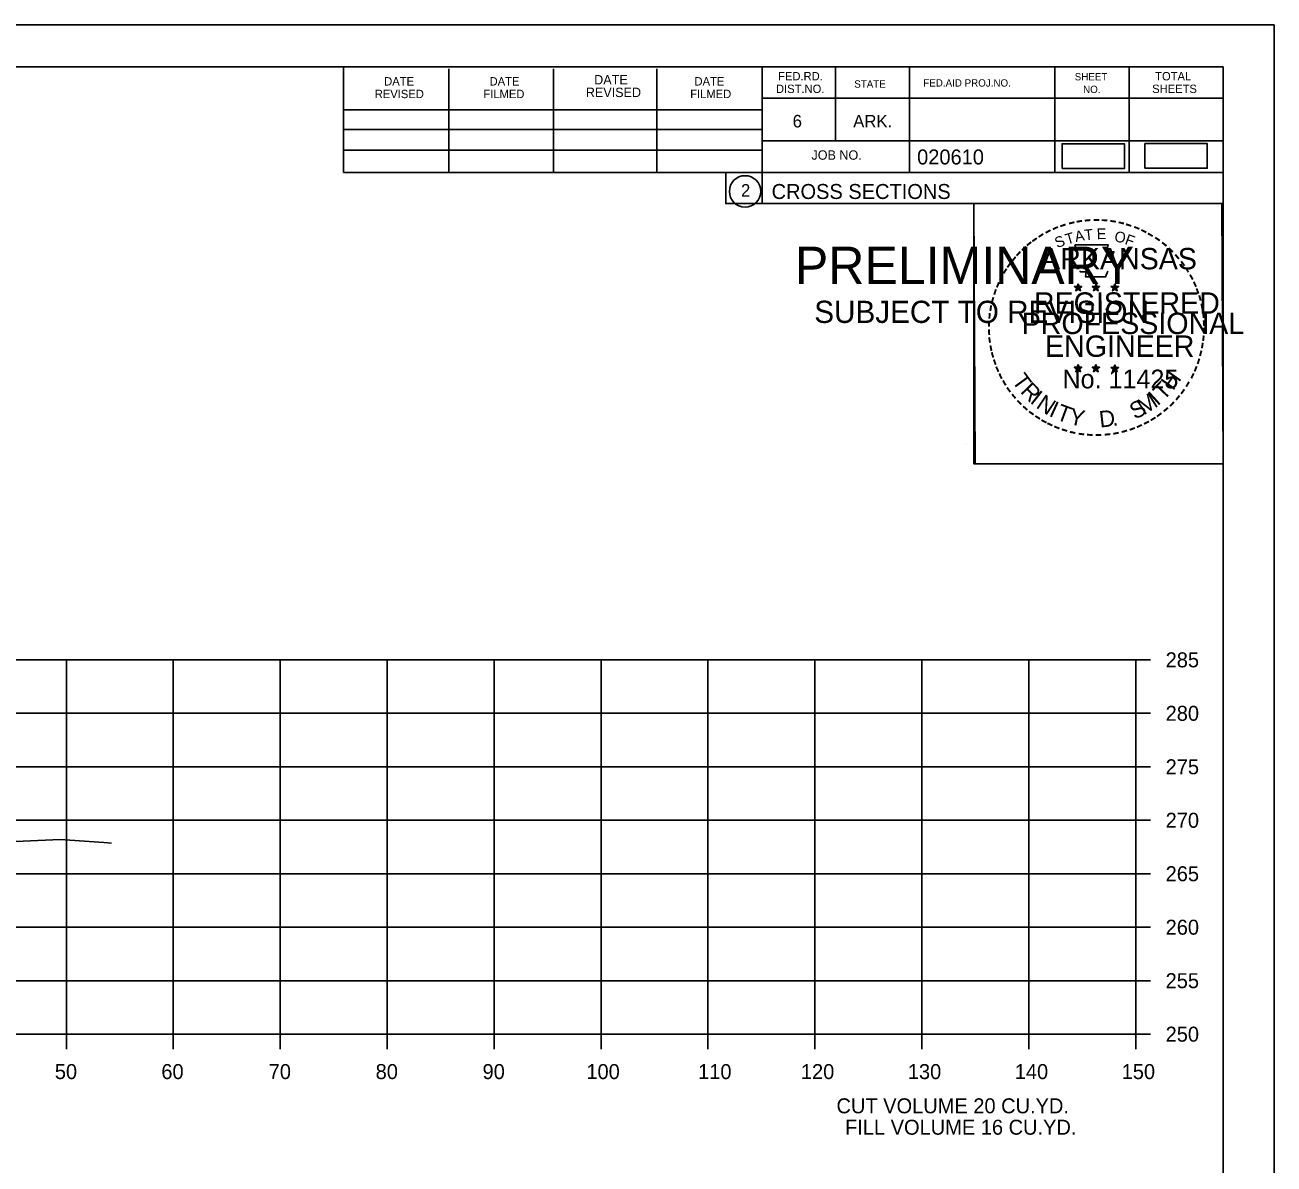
# Model space of a CAD drawing. Extents: x 1103485 to 1107180, y 2010593 to 2011873.
# Drawn here: x 1107063.3 to 1107180.1, y 2010913 to 2011019.5 of the extents above; entities that cross this region are included whole.
import ezdxf

# ---------------------------------------------------------------- set-up
doc = ezdxf.new("R2010")
doc.units = 0
for name, color, linetype in [('R_Axis', 7, 'Continuous'), ('R_Axis Annot', 7, 'Continuous'), ('R_Border', 7, 'Continuous'), ('R_Border PE', 7, 'Continuous'), ('R_Border Prem', 7, 'Continuous'), ('R_Exist Surface', 7, 'Continuous'), ('R_Grid', 7, 'Continuous'), ('R_No Plot', 7, 'Continuous'), ('R_Water', 7, 'Continuous')]:
    doc.layers.add(name, color=color, linetype=linetype)

msp = doc.modelspace()

# ---------------------------------------------------------------- linework, layer by layer
at = {"layer": 'R_Axis'}
for p, q in [((1107167.18, 2010925.15), (1107167.18, 2010960.15)), ((1107168.58, 2010960.15), (1107167.18, 2010960.15)), ((1107168.58, 2010955.15), (1107167.18, 2010955.15)), ((1107168.58, 2010950.15), (1107167.18, 2010950.15)), ((1107168.58, 2010945.15), (1107167.18, 2010945.15)), ((1107168.58, 2010940.15), (1107167.18, 2010940.15)), ((1107168.58, 2010935.15), (1107167.18, 2010935.15)), ((1107168.58, 2010930.15), (1107167.18, 2010930.15)), ((1106867.18, 2010925.15), (1107167.18, 2010925.15)), ((1107067.18, 2010923.75), (1107067.18, 2010925.15)), ((1107077.18, 2010923.75), (1107077.18, 2010925.15)), ((1107087.18, 2010923.75), (1107087.18, 2010925.15)), ((1107097.18, 2010923.75), (1107097.18, 2010925.15)), ((1107107.18, 2010923.75), (1107107.18, 2010925.15)), ((1107117.18, 2010923.75), (1107117.18, 2010925.15)), ((1107127.18, 2010923.75), (1107127.18, 2010925.15)), ((1107137.18, 2010923.75), (1107137.18, 2010925.15)), ((1107147.18, 2010923.75), (1107147.18, 2010925.15)), ((1107157.18, 2010923.75), (1107157.18, 2010925.15)), ((1107167.18, 2010923.75), (1107167.18, 2010925.15)), ((1107168.58, 2010925.15), (1107167.18, 2010925.15))]:
    msp.add_line(p, q, dxfattribs=at)
at = {"layer": 'R_Border'}
for p, q in [((1106859.18, 2011015.61), (1107175.36, 2011015.61)), ((1107093.1, 2011005.73), (1107093.1, 2011015.61)), ((1107132.26, 2011015.61), (1107132.26, 2011002.81)), ((1107139.1, 2011015.61), (1107139.1, 2011008.67)), ((1107146.04, 2011015.61), (1107146.04, 2011005.73)), ((1107159.62, 2011015.61), (1107159.62, 2011005.73)), ((1107166.56, 2011015.61), (1107166.56, 2011005.73)), ((1107175.36, 2010810.15), (1107175.36, 2011015.61)), ((1107102.96, 2011005.73), (1107102.96, 2011015.41)), ((1107112.72, 2011005.73), (1107112.72, 2011015.41)), ((1107122.4, 2011005.73), (1107122.4, 2011015.41)), ((1107175.36, 2011012.67), (1107132.26, 2011012.67)), ((1107175.36, 2011012.69), (1107175.36, 2011012.69)), ((1107093.1, 2011011.59), (1107132.26, 2011011.59)), ((1107093.1, 2011009.73), (1107132.26, 2011009.73)), ((1107175.36, 2011008.67), (1107132.26, 2011008.67)), ((1107135.22, 2011008.67), (1107175.36, 2011008.67)), ((1107093.1, 2011005.73), (1107093.1, 2011007.79)), ((1107093.1, 2011007.79), (1107132.26, 2011007.79)), ((1107175.36, 2011005.73), (1107093.1, 2011005.73)), ((1107132.26, 2011002.81), (1107175.36, 2011002.81))]:
    msp.add_line(p, q, dxfattribs=at)
msp.add_circle((1107130.65, 2011003.95), 1.47, dxfattribs=at)
at = {"layer": 'R_Border PE'}
for p, q in [((1107161.45, 2010995.07), (1107161.8, 2010994.96)), ((1107161.45, 2010995.07), (1107161.7, 2010995.02)), ((1107161.45, 2010995.07), (1107161.69, 2010994.95)), ((1107161.58, 2010994.66), (1107161.8, 2010994.96)), ((1107161.58, 2010994.66), (1107161.71, 2010994.91)), ((1107161.58, 2010994.66), (1107161.8, 2010994.88)), ((1107161.8, 2010995.32), (1107161.76, 2010995.07)), ((1107161.8, 2010994.96), (1107161.8, 2010995.32)), ((1107161.8, 2010995.32), (1107161.85, 2010995.07)), ((1107162.14, 2010995.07), (1107161.8, 2010994.96)), ((1107162.01, 2010994.66), (1107161.8, 2010994.96)), ((1107162.01, 2010994.66), (1107161.8, 2010994.88)), ((1107162.14, 2010995.07), (1107161.86, 2010995.02)), ((1107162.01, 2010994.66), (1107161.87, 2010994.95)), ((1107162.14, 2010995.07), (1107161.94, 2010994.97)), ((1107163.12, 2010995.07), (1107163.47, 2010994.96)), ((1107163.12, 2010995.07), (1107163.37, 2010995.02)), ((1107163.12, 2010995.07), (1107163.36, 2010994.95)), ((1107163.25, 2010994.66), (1107163.47, 2010994.96)), ((1107163.25, 2010994.66), (1107163.38, 2010994.91)), ((1107163.25, 2010994.66), (1107163.47, 2010994.88)), ((1107163.47, 2010995.32), (1107163.43, 2010995.07)), ((1107163.47, 2010994.96), (1107163.47, 2010995.32)), ((1107163.47, 2010995.32), (1107163.52, 2010995.07)), ((1107163.81, 2010995.07), (1107163.47, 2010994.96)), ((1107163.68, 2010994.66), (1107163.47, 2010994.96)), ((1107163.68, 2010994.66), (1107163.47, 2010994.88)), ((1107163.81, 2010995.07), (1107163.53, 2010995.02)), ((1107163.68, 2010994.66), (1107163.54, 2010994.95)), ((1107163.81, 2010995.07), (1107163.61, 2010994.97)), ((1107164.88, 2010995.06), (1107165.23, 2010994.95)), ((1107164.88, 2010995.06), (1107165.14, 2010995.01)), ((1107164.88, 2010995.06), (1107165.12, 2010994.94)), ((1107165.02, 2010994.65), (1107165.23, 2010994.95)), ((1107165.02, 2010994.65), (1107165.14, 2010994.89)), ((1107165.02, 2010994.65), (1107165.23, 2010994.87)), ((1107165.23, 2010995.31), (1107165.19, 2010995.06)), ((1107165.23, 2010994.95), (1107165.23, 2010995.31)), ((1107165.23, 2010995.31), (1107165.28, 2010995.06)), ((1107165.58, 2010995.06), (1107165.23, 2010994.95)), ((1107165.44, 2010994.65), (1107165.23, 2010994.95)), ((1107165.44, 2010994.65), (1107165.23, 2010994.86)), ((1107165.58, 2010995.06), (1107165.29, 2010995.01)), ((1107165.44, 2010994.65), (1107165.31, 2010994.94)), ((1107165.58, 2010995.06), (1107165.37, 2010994.96)), ((1107161.79, 2010987.75), (1107161.75, 2010987.5)), ((1107161.79, 2010987.39), (1107161.79, 2010987.75)), ((1107161.79, 2010987.75), (1107161.84, 2010987.5)), ((1107163.46, 2010987.75), (1107163.42, 2010987.5)), ((1107163.46, 2010987.39), (1107163.46, 2010987.75)), ((1107163.46, 2010987.75), (1107163.51, 2010987.5)), ((1107165.23, 2010987.74), (1107165.19, 2010987.49)), ((1107165.23, 2010987.38), (1107165.23, 2010987.74)), ((1107165.23, 2010987.74), (1107165.28, 2010987.49)), ((1107161.44, 2010987.5), (1107161.79, 2010987.39)), ((1107161.44, 2010987.5), (1107161.7, 2010987.45)), ((1107161.44, 2010987.5), (1107161.68, 2010987.37)), ((1107161.58, 2010987.09), (1107161.79, 2010987.39)), ((1107161.58, 2010987.09), (1107161.7, 2010987.33)), ((1107161.58, 2010987.09), (1107161.79, 2010987.31)), ((1107162.14, 2010987.5), (1107161.79, 2010987.39)), ((1107162.01, 2010987.09), (1107161.79, 2010987.39)), ((1107162.01, 2010987.09), (1107161.79, 2010987.3)), ((1107162.14, 2010987.5), (1107161.85, 2010987.45)), ((1107162.01, 2010987.09), (1107161.87, 2010987.38)), ((1107162.14, 2010987.5), (1107161.94, 2010987.39)), ((1107163.11, 2010987.5), (1107163.46, 2010987.39)), ((1107163.11, 2010987.5), (1107163.37, 2010987.45)), ((1107163.11, 2010987.5), (1107163.35, 2010987.37)), ((1107163.25, 2010987.09), (1107163.46, 2010987.39)), ((1107163.25, 2010987.09), (1107163.37, 2010987.33)), ((1107163.25, 2010987.09), (1107163.46, 2010987.31)), ((1107163.81, 2010987.5), (1107163.46, 2010987.39)), ((1107163.68, 2010987.09), (1107163.46, 2010987.39)), ((1107163.68, 2010987.09), (1107163.46, 2010987.3)), ((1107163.81, 2010987.5), (1107163.52, 2010987.45)), ((1107163.68, 2010987.09), (1107163.54, 2010987.38)), ((1107163.81, 2010987.5), (1107163.61, 2010987.39)), ((1107164.88, 2010987.49), (1107165.23, 2010987.38)), ((1107164.88, 2010987.49), (1107165.13, 2010987.44)), ((1107164.88, 2010987.49), (1107165.12, 2010987.36)), ((1107165.01, 2010987.08), (1107165.23, 2010987.38)), ((1107165.01, 2010987.08), (1107165.14, 2010987.32)), ((1107165.01, 2010987.08), (1107165.23, 2010987.3)), ((1107165.58, 2010987.49), (1107165.23, 2010987.38)), ((1107165.44, 2010987.08), (1107165.23, 2010987.38)), ((1107165.44, 2010987.08), (1107165.23, 2010987.29)), ((1107165.58, 2010987.49), (1107165.29, 2010987.44)), ((1107165.44, 2010987.08), (1107165.31, 2010987.37)), ((1107165.58, 2010987.49), (1107165.37, 2010987.38))]:
    msp.add_line(p, q, dxfattribs=at)
for points in [[(1107161.49, 2010998.95), (1107161.76, 2010998.12)], [(1107165, 2010998.03), (1107165.14, 2010998.31), (1107164.46, 2010998.29), (1107164.61, 2010998.95), (1107161.49, 2010998.95)], [(1107161.98, 2010996.52), (1107161.98, 2010996.44), (1107162.54, 2010996.42), (1107162.49, 2010995.95), (1107164.36, 2010995.95), (1107164.56, 2010996.48)], [(1107161.8, 2010995.32), (1107162.01, 2010994.66), (1107161.45, 2010995.07), (1107162.14, 2010995.07), (1107161.58, 2010994.66), (1107161.8, 2010995.32)], [(1107163.47, 2010995.32), (1107163.68, 2010994.66), (1107163.12, 2010995.07), (1107163.81, 2010995.07), (1107163.25, 2010994.66), (1107163.47, 2010995.32)], [(1107165.23, 2010995.31), (1107165.44, 2010994.65), (1107164.88, 2010995.06), (1107165.58, 2010995.06), (1107165.02, 2010994.65), (1107165.23, 2010995.31)], [(1107161.79, 2010987.75), (1107162.01, 2010987.09), (1107161.44, 2010987.5), (1107162.14, 2010987.5), (1107161.58, 2010987.09), (1107161.79, 2010987.75)], [(1107163.46, 2010987.75), (1107163.68, 2010987.09), (1107163.11, 2010987.5), (1107163.81, 2010987.5), (1107163.25, 2010987.09), (1107163.46, 2010987.75)], [(1107165.23, 2010987.74), (1107165.44, 2010987.08), (1107164.88, 2010987.49), (1107165.58, 2010987.49), (1107165.01, 2010987.08), (1107165.23, 2010987.74)]]:
    msp.add_lwpolyline(points, dxfattribs=at)
for centre, radius in [((1107161.8, 2010994.96), 0.172), ((1107161.8, 2010994.96), 0.145), ((1107161.8, 2010994.96), 0.116), ((1107161.8, 2010994.96), 0.0991), ((1107161.8, 2010994.96), 0.0747), ((1107161.8, 2010994.96), 0.0495), ((1107161.8, 2010994.96), 0.0296), ((1107163.47, 2010994.96), 0.172), ((1107163.47, 2010994.96), 0.145), ((1107163.47, 2010994.96), 0.116), ((1107163.47, 2010994.96), 0.0991), ((1107163.47, 2010994.96), 0.0747), ((1107163.47, 2010994.96), 0.0495), ((1107163.47, 2010994.96), 0.0296), ((1107165.23, 2010994.95), 0.172), ((1107165.23, 2010994.95), 0.145), ((1107165.23, 2010994.95), 0.116), ((1107165.23, 2010994.95), 0.0991), ((1107165.23, 2010994.95), 0.0747), ((1107165.23, 2010994.95), 0.0495), ((1107165.23, 2010994.95), 0.0296), ((1107161.79, 2010987.38), 0.172), ((1107161.79, 2010987.38), 0.145), ((1107163.46, 2010987.38), 0.172), ((1107163.46, 2010987.38), 0.145), ((1107165.23, 2010987.37), 0.172), ((1107165.23, 2010987.37), 0.145), ((1107161.79, 2010987.38), 0.116), ((1107161.79, 2010987.38), 0.0991), ((1107161.79, 2010987.38), 0.0747), ((1107161.79, 2010987.38), 0.0495), ((1107161.79, 2010987.38), 0.0296), ((1107163.46, 2010987.38), 0.116), ((1107163.46, 2010987.38), 0.0991), ((1107163.46, 2010987.38), 0.0747), ((1107163.46, 2010987.38), 0.0495), ((1107163.46, 2010987.38), 0.0296), ((1107165.23, 2010987.37), 0.116), ((1107165.23, 2010987.37), 0.0991), ((1107165.23, 2010987.37), 0.0747), ((1107165.23, 2010987.37), 0.0495), ((1107165.23, 2010987.37), 0.0296)]:
    msp.add_circle(centre, radius, dxfattribs=at)
at = {"layer": 'R_Exist Surface'}
msp.add_lwpolyline([(1107050.66, 2010942.63), (1107066.6, 2010943.35), (1107070.69, 2010943.07), (1107071.4, 2010943.01)], dxfattribs=at)
at = {"layer": 'R_Grid'}
for p, q in [((1106867.18, 2010960.15), (1107167.18, 2010960.15)), ((1107067.18, 2010925.15), (1107067.18, 2010960.15)), ((1107077.18, 2010925.15), (1107077.18, 2010960.15)), ((1107087.18, 2010925.15), (1107087.18, 2010960.15)), ((1107097.18, 2010925.15), (1107097.18, 2010960.15)), ((1107107.18, 2010925.15), (1107107.18, 2010960.15)), ((1107117.18, 2010925.15), (1107117.18, 2010960.15)), ((1107127.18, 2010925.15), (1107127.18, 2010960.15)), ((1107137.18, 2010925.15), (1107137.18, 2010960.15)), ((1107147.18, 2010925.15), (1107147.18, 2010960.15)), ((1107157.18, 2010925.15), (1107157.18, 2010960.15)), ((1107167.18, 2010925.15), (1107167.18, 2010960.15)), ((1106867.18, 2010955.15), (1107167.18, 2010955.15)), ((1106867.18, 2010950.15), (1107167.18, 2010950.15)), ((1106867.18, 2010945.15), (1107167.18, 2010945.15)), ((1106867.18, 2010940.15), (1107167.18, 2010940.15)), ((1106867.18, 2010935.15), (1107167.18, 2010935.15)), ((1106867.18, 2010930.15), (1107167.18, 2010930.15)), ((1106867.18, 2010925.15), (1107167.18, 2010925.15))]:
    msp.add_line(p, q, dxfattribs=at)
at = {"layer": 'R_No Plot'}
for p, q in [((1106846.78, 2011019.51), (1107180.12, 2011019.51)), ((1107151.4, 2010980.36), (1107151.4, 2010980.36))]:
    msp.add_line(p, q, dxfattribs=at)
for points in [[(1106846.78, 2011019.51), (1107180.12, 2011019.51), (1107180.12, 2010806.17), (1106846.78, 2010806.17)], [(1107093.1, 2011015.61), (1107093.1, 2011005.73), (1107128.84, 2011005.73), (1107128.84, 2011002.81), (1107152.04, 2011002.81), (1107152.04, 2010978.48), (1107175.36, 2010978.48), (1107175.36, 2010810.15), (1106859.18, 2010810.15), (1106859.18, 2011015.61)], [(1107152.04, 2011002.81), (1107175.24, 2011002.81), (1107175.36, 2010978.48), (1107152.16, 2010978.48)]]:
    msp.add_lwpolyline(points, close=True, dxfattribs=at)
at = {"layer": 'R_Water'}
for points in [[(1107160.3, 2011006.09), (1107166.13, 2011006.09), (1107166.13, 2011008.4), (1107160.3, 2011008.4)], [(1107168.04, 2011006.11), (1107173.87, 2011006.11), (1107173.87, 2011008.42), (1107168.04, 2011008.42)]]:
    msp.add_lwpolyline(points, close=True, dxfattribs=at)

# ---------------------------------------------------------------- texts
at = {"layer": 'R_Axis Annot'}
for s, p in [('285', (1107169.98, 2010959.45)), ('280', (1107169.98, 2010954.45)), ('275', (1107169.98, 2010949.45)), ('270', (1107169.98, 2010944.45)), ('265', (1107169.98, 2010939.45)), ('260', (1107169.98, 2010934.45)), ('255', (1107169.98, 2010929.45)), ('250', (1107169.98, 2010924.45)), ('50', (1107066.1, 2010920.95)), ('60', (1107076.06, 2010920.95)), ('70', (1107086.1, 2010920.95)), ('80', (1107096.1, 2010920.95)), ('90', (1107106.1, 2010920.95)), ('100', (1107115.81, 2010920.95)), ('110', (1107126.26, 2010920.95)), ('120', (1107135.87, 2010920.95)), ('130', (1107145.87, 2010920.95)), ('140', (1107155.87, 2010920.95)), ('150', (1107165.87, 2010920.95)), ('CUT VOLUME 20 CU.YD.', (1107139.2, 2010917.75)), ('FILL VOLUME 16 CU.YD.', (1107140, 2010915.75))]:
    msp.add_text(s, height=1.4, dxfattribs=at).set_placement(p)
at = {"layer": 'R_Border'}
for s, height, p in [('DATE', 0.782, (1107096.9, 2011013.85)), ('DATE', 0.782, (1107106.76, 2011013.85)), ('DATE', 0.879, (1107116.54, 2011013.95)), ('DATE', 0.782, (1107125.92, 2011013.85)), ('FED.RD.', 0.782, (1107133.74, 2011014.33)), ('FED.AID PROJ.NO.', 0.684, (1107147.32, 2011013.75)), ('SHEET', 0.684, (1107161.48, 2011014.33)), ('TOTAL', 0.782, (1107169, 2011014.33)), ('REVISED', 0.782, (1107096.02, 2011012.67)), ('FILMED', 0.782, (1107106.18, 2011012.67)), ('REVISED', 0.879, (1107115.76, 2011012.77)), ('FILMED', 0.782, (1107125.52, 2011012.67)), ('DIST.NO.', 0.782, (1107133.54, 2011013.15)), ('STATE', 0.684, (1107140.86, 2011013.65)), ('NO.', 0.684, (1107162.26, 2011013.15)), ('SHEETS', 0.782, (1107168.72, 2011013.15)), ('6', 1.17, (1107135.1, 2011009.93)), ('ARK.', 1.172, (1107140.76, 2011009.93)), ('JOB NO.', 0.879, (1107136.86, 2011006.91)), ('020610', 1.4, (1107146.74, 2011006.47)), ('2', 1.17, (1107130.27, 2011003.46)), ('CROSS SECTIONS', 1.4, (1107133.13, 2011003.24))]:
    msp.add_text(s, height=height, rotation=360, dxfattribs=at).set_placement(p)
at = {"layer": 'R_Border PE'}
for s, height, rotation, p in [('-', 1.6, 28.7918, (1107158.97, 2010999.49)), ('-', 1.6, 24.3072, (1107159.6, 2010999.81)), ('-', 1.6, 19.1761, (1107160.24, 2011000.07)), ('-', 1.6, 13.6301, (1107160.99, 2011000.32)), ('-', 1.6, 10.2193, (1107161.67, 2011000.48)), ('T', 1, 6.0228, (1107162.43, 2010999.37)), ('-', 1.6, 5.8968, (1107162.39, 2011000.59)), ('-', 1.6, 0.1862, (1107163.17, 2011000.66)), ('E', 1, 0.8323, (1107163.54, 2010999.48)), ('-', 1.6, 357.743, (1107163.89, 2011000.65)), ('-', 1.6, 352.1617, (1107164.63, 2011000.59)), ('-', 1.6, 347.2049, (1107165.35, 2011000.48)), ('-', 1.6, 342.3362, (1107165.99, 2011000.32)), ('-', 1.6, 337.8551, (1107166.72, 2011000.1)), ('-', 1.6, 334.1211, (1107167.35, 2010999.83)), ('-', 1.6, 38.9507, (1107157.32, 2010998.35)), ('-', 1.6, 36.2317, (1107157.8, 2010998.72)), ('-', 1.6, 34.0636, (1107158.37, 2010999.12)), ('S', 1, 21.594, (1107159.84, 2010998.63)), ('T', 1, 16.4036, (1107160.76, 2010998.96)), ('A', 1, 11.2132, (1107161.58, 2010999.21)), ('O', 1, 350.4515, (1107165.14, 2010999.27)), ('F', 1, 340.0707, (1107166.1, 2010999.05)), ('-', 1.6, 329.6409, (1107167.93, 2010999.54)), ('-', 1.6, 325.8627, (1107168.58, 2010999.18)), ('-', 1.6, 320.5297, (1107169.19, 2010998.76)), ('-', 1.6, 48.423, (1107156.44, 2010997.45)), ('-', 1.6, 42.9622, (1107156.89, 2010997.93)), ('ARKANSAS', 2, 360, (1107158.34, 2010996.66)), ('-', 1.6, 315.5786, (1107169.78, 2010998.27)), ('-', 1.6, 309.8797, (1107170.35, 2010997.72)), ('-', 1.6, 54.2325, (1107155.62, 2010996.4)), ('-', 1.6, 50.6142, (1107156.04, 2010996.96)), ('-', 1.6, 306.6522, (1107170.88, 2010997.12)), ('-', 1.6, 62.8713, (1107154.98, 2010995.26)), ('-', 1.6, 58.0706, (1107155.3, 2010995.87)), ('-', 1.4, 303.6753, (1107171.36, 2010996.55)), ('-', 1.6, 299.6684, (1107171.68, 2010995.94)), ('-', 1.6, 72.3945, (1107154.51, 2010994.02)), ('-', 1.6, 67.7743, (1107154.73, 2010994.65)), ('REGISTERED', 2, 360, (1107157.66, 2010992.51)), ('DWB', 0.01, 360, (1107161.78, 2010994.95)), ('DWB', 0.01, 360, (1107163.45, 2010994.95)), ('DWB', 0.01, 360, (1107165.22, 2010994.94)), ('-', 1.6, 294.6628, (1107172.01, 2010995.33)), ('-', 1.6, 290.5728, (1107172.26, 2010994.75)), ('-', 1.6, 75.461, (1107154.31, 2010993.3)), ('-', 1.6, 285.1233, (1107172.5, 2010994.17)), ('-', 1.6, 280.5493, (1107172.7, 2010993.43)), ('-', 1.6, 85.1863, (1107154.1, 2010991.9)), ('-', 1.6, 81.2013, (1107154.18, 2010992.59)), ('PROFESSIONAL', 2, 360, (1107156.52, 2010990.61)), ('-', 1.6, 276.5962, (1107172.86, 2010992.66)), ('-', 1.6, 94.1959, (1107154.11, 2010990.47)), ('-', 1.6, 89.0622, (1107154.08, 2010991.2)), ('-', 1.6, 274.3301, (1107172.92, 2010991.94)), ('-', 1.6, 269.9407, (1107172.95, 2010991.31)), ('-', 1.6, 98.9479, (1107154.18, 2010989.8)), ('ENGINEER', 2, 360, (1107158.7, 2010988.48)), ('-', 1.6, 263.5172, (1107172.94, 2010990.64)), ('-', 1.6, 101.7149, (1107154.32, 2010989.07)), ('-', 1.6, 105.4578, (1107154.48, 2010988.48)), ('-', 1.6, 255.7626, (1107172.75, 2010989.31)), ('-', 1.6, 260.9953, (1107172.86, 2010989.99)), ('-', 1.6, 109.0874, (1107154.7, 2010987.85)), ('-', 1.6, 114.0643, (1107154.95, 2010987.25)), ('-', 1.6, 247.8887, (1107172.35, 2010987.92)), ('-', 1.6, 252.8681, (1107172.57, 2010988.59)), ('-', 1.6, 115.7289, (1107155.25, 2010986.63)), ('T', 1.54, 306.0406, (1107155.55, 2010986.22)), ('No. 11425', 1.757, 360, (1107160.33, 2010985.53)), ('DWB', 0.01, 360, (1107161.78, 2010987.38)), ('DWB', 0.01, 360, (1107163.45, 2010987.38)), ('DWB', 0.01, 360, (1107165.22, 2010987.37)), ('H', 1.54, 54.6088, (1107170.67, 2010985.26)), ('-', 1.6, 244.6197, (1107172.09, 2010987.29)), ('-', 1.6, 120.4471, (1107155.61, 2010986.05)), ('-', 1.6, 125.8934, (1107156.01, 2010985.48)), ('R', 1.54, 314.005, (1107156.32, 2010985.18)), ('I', 1.54, 321.9694, (1107157.22, 2010984.24)), ('I', 1.54, 42.1136, (1107169.22, 2010983.84)), ('T', 1.54, 46.6444, (1107169.78, 2010984.32)), ('-', 1.6, 233.8452, (1107171.29, 2010985.88)), ('-', 1.6, 239.0712, (1107171.69, 2010986.54)), ('-', 1.6, 130.7181, (1107156.48, 2010984.93)), ('-', 1.6, 134.2238, (1107156.99, 2010984.39)), ('N', 1.54, 326.5002, (1107157.78, 2010983.77)), ('I', 1.54, 335.3603, (1107158.99, 2010982.99)), ('T', 1.54, 339.8912, (1107159.65, 2010982.66)), ('S', 1.54, 26.9312, (1107167.1, 2010982.59)), ('M', 1.54, 32.6563, (1107167.94, 2010982.99)), ('-', 1.6, 225.7653, (1107170.38, 2010984.75)), ('-', 1.6, 231.2538, (1107170.86, 2010985.32)), ('-', 1.6, 138.9338, (1107157.52, 2010983.92)), ('-', 1.6, 144.6463, (1107158.07, 2010983.52)), ('-', 1.6, 148.0898, (1107158.64, 2010983.15)), ('Y', 1.54, 347.8556, (1107160.87, 2010982.21)), ('D', 1.54, 6.3969, (1107163.85, 2010981.86)), ('-', 1.6, 212.2491, (1107168.78, 2010983.39)), ('-', 1.6, 215.7363, (1107169.31, 2010983.77)), ('-', 1.6, 221.0851, (1107169.86, 2010984.25)), ('-', 1.6, 151.5704, (1107159.21, 2010982.82)), ('-', 1.6, 154.6002, (1107159.74, 2010982.57)), ('-', 1.6, 158.5612, (1107160.36, 2010982.32)), ('-', 1.6, 162.7983, (1107161.05, 2010982.11)), ('.', 1.54, 13.7642, (1107165.05, 2010981.98)), ('-', 1.6, 200.7184, (1107166.98, 2010982.45)), ('-', 1.6, 204.2516, (1107167.6, 2010982.72)), ('-', 1.6, 207.3568, (1107168.22, 2010983.04)), ('-', 1.6, 167.5555, (1107161.76, 2010981.94)), ('-', 1.6, 173.1155, (1107162.53, 2010981.83)), ('-', 1.6, 176.5183, (1107163.28, 2010981.78)), ('-', 1.6, 181.5918, (1107164.03, 2010981.8)), ('-', 1.6, 185.8167, (1107164.84, 2010981.88)), ('-', 1.6, 191.2858, (1107165.57, 2010982.01)), ('-', 1.6, 195.4743, (1107166.3, 2010982.21))]:
    msp.add_text(s, height=height, rotation=rotation, dxfattribs=at).set_placement(p)
at = {"layer": 'R_Border Prem'}
for s, height, p in [('PRELIMINARY', 3.5, (1107135.31, 2010995.28)), ('DWB', 0.01, (1107136.06, 2010997.13)), ('SUBJECT TO REVISION', 2.0751, (1107137.12, 2010991.65))]:
    msp.add_text(s, height=height, rotation=360, dxfattribs=at).set_placement(p)

doc.saveas('drawing.dxf')
